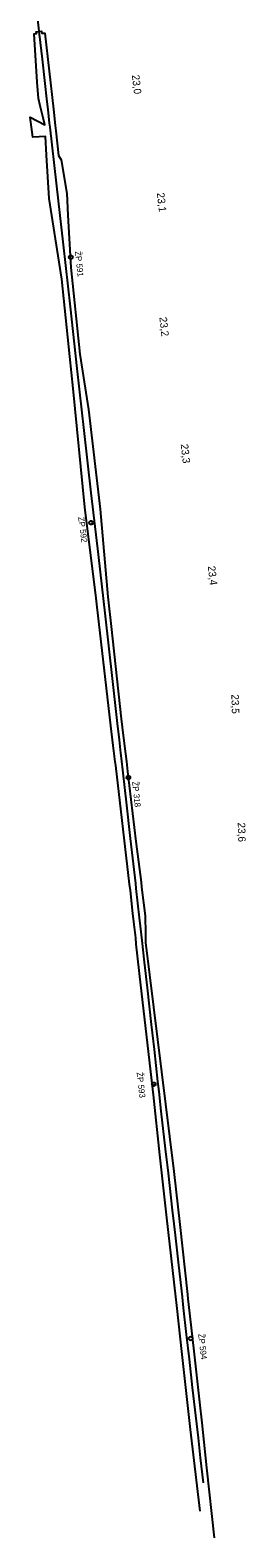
# Model space of a CAD drawing. Extents: x -792643 to -787072, y -1118436 to -1109677.
# Drawn here: x -792617 to -792445, y -1111624 to -1110414 of the extents above; entities that cross this region are included whole.
import ezdxf

# ---------------------------------------------------------------- set-up
doc = ezdxf.new("R2010")
doc.units = 0
for name, color, linetype in [('Vrstva 1', 7, 'Continuous'), ('Vrstva 53', 7, 'Continuous'), ('Vrstva 63', 7, 'Continuous'), ('Vrstva 7', 7, 'Continuous')]:
    doc.layers.add(name, color=color, linetype=linetype)

msp = doc.modelspace()

# ---------------------------------------------------------------- linework, layer by layer
at = {"layer": 'Vrstva 1'}
for p, q in [((-792518.2, -1111231.8), (-792515.4, -1111257.4)), ((-792515.4, -1111257.4), (-792514.9, -1111261.4)), ((-792514.9, -1111261.4), (-792514.5, -1111265.4)), ((-792509.3, -1111311.4), (-792507, -1111331)), ((-792502.4, -1111371.6), (-792501.4, -1111380.7)), ((-792494.8, -1111439), (-792492.4, -1111460.5))]:
    msp.add_line(p, q, dxfattribs=at)
for points in [[(-792614.8, -1110376.5), (-792611, -1110409.6), (-792610.2, -1110416.9)], [(-792610.2, -1110416.9), (-792607.9, -1110436.9), (-792604.1, -1110471.2), (-792603.4, -1110477.3), (-792602.2, -1110488.3), (-792601.8, -1110491.4), (-792596.7, -1110536.3), (-792591.1, -1110586), (-792585.5, -1110635.6), (-792580, -1110685.2), (-792574.4, -1110735), (-792568.8, -1110784.8), (-792563.1, -1110834.3), (-792557.5, -1110884), (-792551.9, -1110933.9), (-792547.8, -1110970.1), (-792546.3, -1110983.3), (-792545.1, -1110993.9), (-792544.6, -1110998), (-792540.7, -1111033.2), (-792537.3, -1111062.4)], [(-792537.3, -1111062.4), (-792535, -1111082.6), (-792533.2, -1111098.6), (-792532.8, -1111102.6), (-792530.1, -1111126), (-792529.4, -1111132.6), (-792528.1, -1111144.2)], [(-792528.1, -1111144.2), (-792526.1, -1111161.7), (-792523.8, -1111182.2), (-792520.5, -1111211.6), (-792518.2, -1111231.8)], [(-792514.5, -1111265.4), (-792512.7, -1111281.3), (-792509.3, -1111311.4)], [(-792507, -1111331), (-792503.7, -1111360.6), (-792502.4, -1111371.6)], [(-792501.4, -1111380.7), (-792498.7, -1111404.7), (-792495.8, -1111430.3), (-792495.8, -1111430.6), (-792494.8, -1111439)], [(-792492.4, -1111460.5), (-792490.1, -1111480.2), (-792487.6, -1111503)], [(-792487.6, -1111503), (-792483, -1111543.5), (-792481.2, -1111559.4)], [(-792481.2, -1111559.4), (-792478.9, -1111579.6)]]:
    msp.add_lwpolyline(points, dxfattribs=at)
at = {"layer": 'Vrstva 53'}
for points in [[(-792611.8, -1110455.3), (-792614.4, -1110416.4), (-792614.4, -1110416.4), (-792612.5, -1110416.3), (-792612.7, -1110415), (-792608.4, -1110414.5), (-792608.2, -1110416.1), (-792605.8, -1110416), (-792598.7, -1110476.9)], [(-792481.2, -1111602.3), (-792489, -1111536.8), (-792495.6, -1111476.5), (-792499.9, -1111437.3), (-792500.9, -1111430.2), (-792508.1, -1111366.7), (-792513.6, -1111316.2), (-792518.8, -1111268), (-792528.8, -1111180.1), (-792532.6, -1111147.1), (-792532.9, -1111142.2), (-792534.5, -1111129.2), (-792535.3, -1111122.6), (-792537.1, -1111104.1), (-792537.9, -1111098.9), (-792549, -1111003.8), (-792549.6, -1110998.9), (-792549.9, -1110996.2), (-792550.9, -1110987.8), (-792552.8, -1110972), (-792564.1, -1110874.3), (-792564.7, -1110869.5), (-792573.7, -1110796.5), (-792583.1, -1110701.1), (-792585.7, -1110675.6), (-792592.2, -1110613.5), (-792602.4, -1110548.8), (-792604.4, -1110514), (-792605.3, -1110498.8), (-792615.3, -1110499.5), (-792617.5, -1110483.3), (-792605.8, -1110489.5), (-792606.9, -1110485), (-792609.5, -1110474.3), (-792610.9, -1110468.4), (-792611.8, -1110455.3)], [(-792598.7, -1110476.9), (-792597.4, -1110490), (-792596.9, -1110494.3), (-792594.9, -1110514.1), (-792592.7, -1110517.6), (-792588.2, -1110544.6), (-792587.2, -1110562.1), (-792585, -1110604.1), (-792577.7, -1110673.7), (-792570.9, -1110718.1), (-792561.4, -1110798), (-792555.3, -1110868.4), (-792552.7, -1110892.2), (-792544.5, -1110966.2), (-792542.9, -1110979.7), (-792541.2, -1110994.4), (-792540.4, -1111000.6), (-792539.5, -1111008.6), (-792532.9, -1111064.7), (-792528.7, -1111097.3), (-792528.2, -1111101.5), (-792525.3, -1111124.4), (-792525.1, -1111138.9), (-792525, -1111143.7), (-792525, -1111145.7), (-792505.9, -1111301.5), (-792502.5, -1111329.5), (-792497.7, -1111372.2), (-792491.5, -1111428.3), (-792491.1, -1111431.8), (-792490.6, -1111436.3), (-792486.5, -1111473.8), (-792481.9, -1111514.9), (-792480.1, -1111531.4), (-792479.3, -1111539.2), (-792476.2, -1111567.4), (-792470.2, -1111623.7)]]:
    msp.add_lwpolyline(points, dxfattribs=at)
at = {"layer": 'Vrstva 63'}
for p, q in [((-792585, -1110595.9), (-792584.8, -1110595.9)), ((-792568.7, -1110808.9), (-792568.5, -1110808.9)), ((-792538.9, -1111013.5), (-792538.7, -1111013.5)), ((-792518.5, -1111259.5), (-792518.5, -1111259.7)), ((-792488.9, -1111463.6), (-792488.9, -1111463.8))]:
    msp.add_line(p, q, dxfattribs=at)
for centre in [(-792584.9, -1110595.9), (-792568.6, -1110808.9), (-792538.8, -1111013.5), (-792518.5, -1111259.6), (-792488.9, -1111463.7)]:
    msp.add_circle(centre, 1.51, dxfattribs=at)

# ---------------------------------------------------------------- texts
for s, rotation, p in [('ŽP 591', 276.4364, (-792581.7, -1110591.2)), ('ŽP 592', 277.5127, (-792579.1, -1110804.5)), ('ŽP 318', 276, (-792535.8, -1111016.8)), ('ŽP 593', 276.4285, (-792532.2, -1111250.2)), ('ŽP 594', 276.4832, (-792482.9, -1111460.1))]:
    msp.add_text(s, height=4.8, rotation=rotation, dxfattribs=at).set_placement(p)
at = {"layer": 'Vrstva 7'}
for s, rotation, p in [('23,0', 276.4179, (-792536, -1110449.7)), ('23,1', 276.4363, (-792516, -1110544.3)), ('23,2', 276.3867, (-792514, -1110644.1)), ('23,3', 276.4308, (-792496.9, -1110746)), ('23,4', 276.4956, (-792475.2, -1110843.9)), ('23,5', 271.4243, (-792456.3, -1110946.7)), ('23,6', 271.5127, (-792451.2, -1111049.6))]:
    msp.add_text(s, height=6, rotation=rotation, dxfattribs=at).set_placement(p)

doc.saveas('drawing.dxf')
